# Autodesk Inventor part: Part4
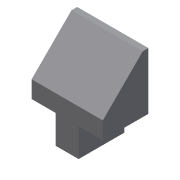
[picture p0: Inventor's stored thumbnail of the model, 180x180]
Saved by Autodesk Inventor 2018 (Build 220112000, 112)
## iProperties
Shininess: 77.0
Length Units: 11269
Angle Units: 11279
Time Units: 11290
Mass Units: 11283
Length Display Precision: 3
Angle Display Precision: 2
Created: 2002-01
Part Number: Part4
Document SubType Name: Modeling
Designer: ***
Density: 1 g/cm^3
Material: Generic
Appearance: Default
Density: 0.0
Volumn: 0.0
Area: 0.0
PropertySet Name: Model Information
Control State: 0
Master: False
Checked Out: False
Author: ***
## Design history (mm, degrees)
sketch "Sketch2"
  geometry: L1 (2.32, -6.969)-(2.32, 13.031); L2 (2.32, 13.031)-(0.32, 13.031); L3 (0.32, 13.031)-(-13.68, -0.969); L4 (-13.68, -0.969)-(-13.68, -6.969); L5 (-13.68, -6.969)-(2.32, -6.969)
  constraints: 10 end point, 2 parallel, 1 perpendicular, 1 vertical
  dimensions: "d0" = 2 distance of L1.end L2.end; "d1" = 135 deg angle of L4 L3; "d2" = 20 distance of L1.start L1.end; "d3" = 16 distance of L4.end L1.start
extrude "Extrusion1" new body sketch "Sketch2" stored distance "d4" = 25; taper "d5" = 0 deg
sketch "Sketch3"
  geometry: L1 (-13.68, -6.969)-(2.32, -6.969); L2 (2.32, -6.969)-(2.32, -16.969); L3 (2.32, -16.969)-(-13.68, -16.969); L4 (-13.68, -16.969)-(-13.68, -6.969); L5 (-13.68, -6.969)-(2.32, -6.969) reference; L6 (-13.68, -0.969)-(-13.68, -6.969) reference; L7 (2.32, -6.969)-(2.32, 13.031) reference
  constraints: 8 end point, 3 collinear, 2 parallel, 1 horizontal, 1 perpendicular
  dimensions: "d6" = 10 distance of L3.end L1.start
extrude "Extrusion2" join sketch "Sketch3" stored distance "d7" = 8; taper "d8" = 0 deg
body "Solid1"
